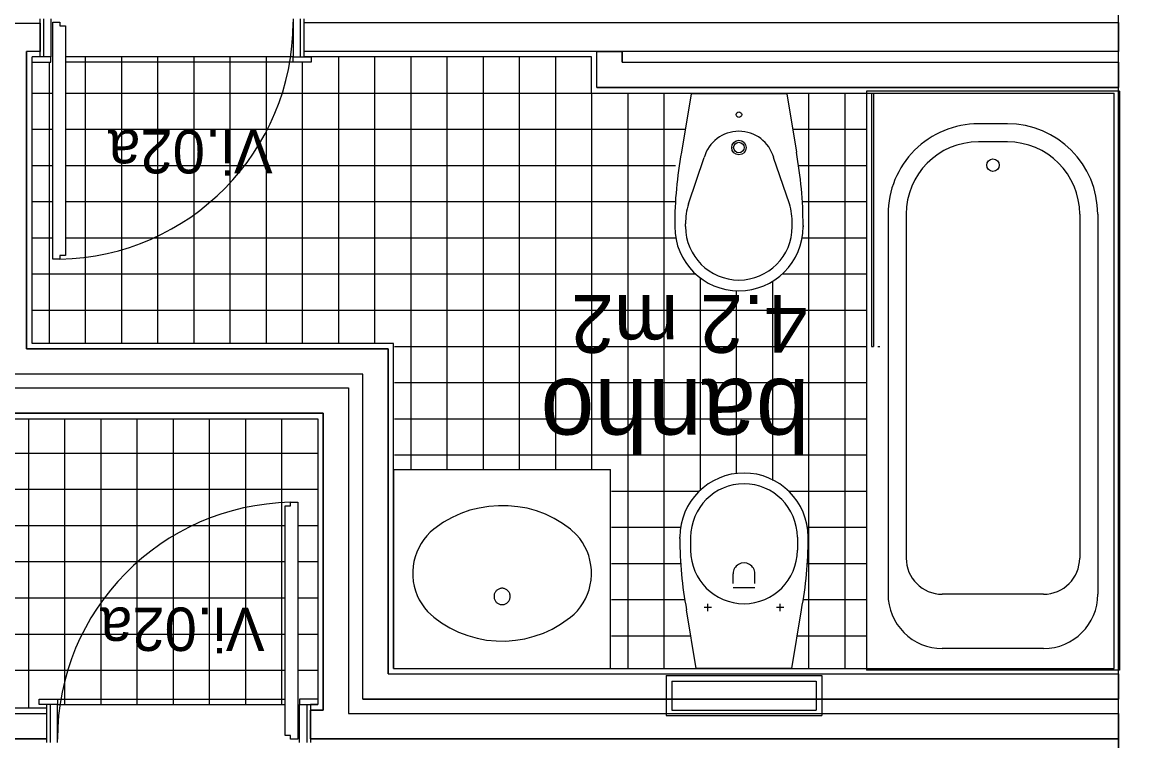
# Model space of a CAD drawing. Extents: x 1278 to 1356, y -253.7 to -224.
# Drawn here: x 1320.769 to 1323.824, y -240.419 to -238.433 of the extents above; entities that cross this region are included whole.
import ezdxf

# ---------------------------------------------------------------- set-up
doc = ezdxf.new("R2010")
doc.units = 0
for name, color, linetype in [('Level 1', 7, 'Continuous'), ('Level 10', 7, 'Continuous'), ('Level 11', 7, 'Continuous'), ('Level 13', 7, 'Continuous'), ('Level 2', 7, 'Continuous'), ('Level 36', 7, 'Continuous'), ('Level 4', 7, 'Continuous'), ('Level 40', 7, 'Continuous'), ('Level 60', 7, 'Continuous'), ('Level 65', 7, 'Continuous'), ('Level 66', 7, 'Continuous'), ('Level 67', 7, 'Continuous')]:
    doc.layers.add(name, color=color, linetype=linetype)

msp = doc.modelspace()

# ---------------------------------------------------------------- linework, layer by layer
at = {"layer": 'Level 1'}
for p, q in [((1320.8183, -238.529), (1320.8183, -238.424)), ((1321.5483, -238.529), (1321.5483, -238.424)), ((1320.7283, -238.4357), (1320.8183, -238.4357)), ((1321.5483, -238.434), (1323.801, -238.434)), ((1320.781, -239.3357), (1320.781, -238.514)), ((1322.3583, -238.514), (1321.5483, -238.514)), ((1323.801, -238.514), (1322.4283, -238.514)), ((1320.8183, -238.529), (1320.796, -238.529)), ((1321.781, -239.3357), (1320.781, -239.3357)), ((1321.781, -240.234), (1321.781, -239.3357)), ((1321.711, -239.4057), (1320.711, -239.4057)), ((1321.711, -240.304), (1321.711, -239.4057)), ((1320.671, -239.444), (1321.671, -239.444)), ((1321.671, -239.444), (1321.671, -240.344)), ((1320.601, -239.514), (1321.601, -239.514)), ((1321.601, -239.514), (1321.601, -240.334)), ((1321.7833, -240.234), (1323.801, -240.234)), ((1320.836, -240.319), (1320.836, -240.424)), ((1321.566, -240.319), (1321.566, -240.424)), ((1321.601, -240.334), (1321.566, -240.334)), ((1321.671, -240.344), (1323.801, -240.344)), ((1320.726, -240.414), (1320.836, -240.414)), ((1321.566, -240.414), (1323.801, -240.414)), ((1323.801, -240.414), (1323.801, -242.034))]:
    msp.add_line(p, q, dxfattribs=at)
at = {"layer": 'Level 10'}
for p, q in [((1320.8433, -238.544), (1320.8433, -239.319)), ((1321.5183, -238.529), (1320.8883, -238.529)), ((1320.9433, -238.529), (1320.9433, -239.319)), ((1321.0433, -238.529), (1321.0433, -239.319)), ((1321.1433, -238.529), (1321.1433, -239.319)), ((1321.2433, -238.529), (1321.2433, -239.319)), ((1321.3433, -238.529), (1321.3433, -239.319)), ((1321.4433, -238.529), (1321.4433, -239.319)), ((1321.5433, -238.544), (1321.5433, -239.319)), ((1321.6433, -238.529), (1321.6433, -239.319)), ((1321.7433, -238.529), (1321.7433, -239.319)), ((1321.8433, -238.529), (1321.8433, -239.669)), ((1321.9433, -238.529), (1321.9433, -239.669)), ((1322.0433, -238.529), (1322.0433, -239.669)), ((1322.1433, -238.529), (1322.1433, -239.669)), ((1322.2433, -238.529), (1322.2433, -239.669)), ((1320.7983, -238.629), (1320.8533, -238.629)), ((1320.8883, -238.629), (1322.602, -238.629)), ((1322.3433, -238.629), (1322.3433, -239.669)), ((1322.4433, -238.629), (1322.4433, -240.219)), ((1322.5433, -238.629), (1322.5433, -240.219)), ((1322.8995, -238.629), (1323.1033, -238.629)), ((1322.9433, -238.629), (1322.9433, -240.219)), ((1323.0433, -238.629), (1323.0433, -240.219)), ((1320.7983, -238.729), (1320.8533, -238.729)), ((1320.8883, -238.729), (1322.6023, -238.729)), ((1322.8992, -238.729), (1323.1033, -238.729)), ((1320.7983, -238.829), (1320.8533, -238.829)), ((1320.8883, -238.829), (1322.5751, -238.829)), ((1322.9158, -238.829), (1323.1033, -238.829)), ((1320.7983, -238.929), (1320.8533, -238.929)), ((1320.8883, -238.929), (1322.5763, -238.929)), ((1322.9253, -238.929), (1323.1033, -238.929)), ((1320.7983, -239.029), (1320.8533, -239.029)), ((1320.8883, -239.029), (1322.576, -239.029)), ((1322.9256, -239.029), (1323.1033, -239.029)), ((1320.7983, -239.129), (1322.6307, -239.129)), ((1322.8708, -239.129), (1323.1033, -239.129)), ((1322.6433, -239.1395), (1322.6433, -239.7272)), ((1322.8433, -239.1502), (1322.8433, -239.7)), ((1322.7433, -239.1756), (1322.7433, -239.6803)), ((1320.7983, -239.229), (1323.1033, -239.229)), ((1321.7983, -239.329), (1323.1033, -239.329)), ((1321.7983, -239.429), (1323.1033, -239.429)), ((1320.786, -239.529), (1320.786, -240.329)), ((1320.886, -239.529), (1320.886, -240.319)), ((1320.986, -239.529), (1320.986, -240.319)), ((1321.086, -239.529), (1321.086, -240.319)), ((1321.186, -239.529), (1321.186, -240.319)), ((1321.286, -239.529), (1321.286, -240.319)), ((1321.386, -239.529), (1321.386, -240.319)), ((1321.486, -239.529), (1321.486, -240.319)), ((1321.7983, -239.529), (1323.1033, -239.529)), ((1319.2103, -239.624), (1321.586, -239.624)), ((1321.7983, -239.629), (1323.1033, -239.629)), ((1319.8012, -239.724), (1321.586, -239.724)), ((1322.3981, -239.729), (1322.6414, -239.729)), ((1322.8884, -239.729), (1323.1033, -239.729)), ((1319.8548, -239.824), (1321.496, -239.824)), ((1321.531, -239.824), (1321.586, -239.824)), ((1322.3981, -239.829), (1322.5895, -239.829)), ((1322.9403, -239.829), (1323.1033, -239.829)), ((1319.853, -239.924), (1321.496, -239.924)), ((1321.531, -239.924), (1321.586, -239.924)), ((1322.3981, -239.929), (1322.5897, -239.929)), ((1322.9401, -239.929), (1323.1033, -239.929)), ((1319.8422, -240.024), (1321.496, -240.024)), ((1321.531, -240.024), (1321.586, -240.024)), ((1322.3981, -240.029), (1322.6014, -240.029)), ((1322.9285, -240.029), (1323.1033, -240.029)), ((1319.8256, -240.124), (1321.496, -240.124)), ((1321.531, -240.124), (1321.586, -240.124)), ((1322.3981, -240.129), (1322.6178, -240.129)), ((1322.912, -240.129), (1323.1033, -240.129)), ((1320.086, -240.224), (1321.496, -240.224)), ((1321.531, -240.224), (1321.586, -240.224)), ((1320.866, -240.319), (1321.496, -240.319))]:
    msp.add_line(p, q, dxfattribs=at)
at = {"layer": 'Level 11'}
for p, q in [((1322.6185, -238.6307), (1322.5918, -238.7928)), ((1322.8831, -238.6307), (1322.6185, -238.6307)), ((1322.8831, -238.6307), (1322.9097, -238.7928)), ((1323.8033, -238.624), (1323.1033, -238.624)), ((1323.1033, -238.624), (1323.1033, -240.224)), ((1323.8033, -238.624), (1323.8033, -240.224)), ((1323.4933, -238.714), (1323.4133, -238.714)), ((1323.4933, -238.764), (1323.4133, -238.764)), ((1322.611, -238.9352), (1322.6546, -238.8073)), ((1322.8906, -238.9352), (1322.8469, -238.8073)), ((1323.1633, -238.964), (1323.1633, -240.014)), ((1323.2133, -238.964), (1323.2133, -239.914)), ((1323.6933, -238.964), (1323.6933, -239.914)), ((1323.7433, -238.964), (1323.7433, -240.014)), ((1322.5733, -238.9949), (1322.5733, -238.9985)), ((1322.6033, -238.9982), (1322.6033, -238.9901)), ((1322.8983, -238.9982), (1322.8983, -238.9901)), ((1322.9283, -238.9949), (1322.9283, -238.9985)), ((1322.0329, -239.7759), (1322.0069, -239.7816)), ((1322.0592, -239.7715), (1322.0329, -239.7759)), ((1322.0858, -239.7694), (1322.0592, -239.7715)), ((1322.1125, -239.7697), (1322.0858, -239.7694)), ((1322.139, -239.7723), (1322.1125, -239.7697)), ((1322.1654, -239.7763), (1322.139, -239.7723)), ((1322.1911, -239.7835), (1322.1654, -239.7763)), ((1321.9574, -239.8017), (1321.9342, -239.8149)), ((1321.9817, -239.7905), (1321.9574, -239.8017)), ((1322.0069, -239.7816), (1321.9817, -239.7905)), ((1322.2161, -239.793), (1322.1911, -239.7835)), ((1322.2401, -239.8047), (1322.2161, -239.793)), ((1322.2631, -239.8184), (1322.2401, -239.8047)), ((1321.9071, -239.8341), (1321.8971, -239.8428)), ((1321.9342, -239.8149), (1321.9071, -239.8341)), ((1322.2848, -239.8341), (1322.2631, -239.8184)), ((1322.302, -239.85), (1322.2848, -239.8341)), ((1321.8794, -239.8628), (1321.8719, -239.8738)), ((1321.8878, -239.8524), (1321.8794, -239.8628)), ((1321.8971, -239.8428), (1321.8878, -239.8524)), ((1322.3106, -239.8602), (1322.302, -239.85)), ((1322.3183, -239.8711), (1322.3106, -239.8602)), ((1322.5874, -239.8598), (1322.5874, -239.8562)), ((1322.6174, -239.8565), (1322.6174, -239.8926)), ((1322.9124, -239.8565), (1322.9124, -239.8926)), ((1322.9424, -239.8598), (1322.9424, -239.8562)), ((1321.8599, -239.8977), (1321.8555, -239.9104)), ((1321.8654, -239.8855), (1321.8599, -239.8977)), ((1321.8719, -239.8738), (1321.8654, -239.8855)), ((1322.3251, -239.8827), (1322.3183, -239.8711)), ((1322.3308, -239.8948), (1322.3251, -239.8827)), ((1322.3355, -239.9073), (1322.3308, -239.8948)), ((1321.8522, -239.9234), (1321.85, -239.9366)), ((1321.8555, -239.9104), (1321.8522, -239.9234)), ((1322.339, -239.9202), (1322.3355, -239.9073)), ((1322.3415, -239.9334), (1322.339, -239.9202)), ((1321.85, -239.9366), (1321.849, -239.95)), ((1321.849, -239.95), (1321.8491, -239.9638)), ((1322.3428, -239.9468), (1322.3415, -239.9334)), ((1322.3419, -239.9753), (1322.3429, -239.9606)), ((1322.3429, -239.9606), (1322.3428, -239.9468)), ((1322.7349, -239.9845), (1322.7349, -239.9572)), ((1322.7949, -239.9845), (1322.7949, -239.9573)), ((1321.8491, -239.9638), (1321.8504, -239.9784)), ((1321.8504, -239.9784), (1321.8529, -239.9916)), ((1322.3364, -240.0015), (1322.3397, -239.9885)), ((1322.3397, -239.9885), (1322.3419, -239.9753)), ((1321.8529, -239.9916), (1321.8564, -240.0045)), ((1321.8564, -240.0045), (1321.8611, -240.0171)), ((1321.8611, -240.0171), (1321.8668, -240.0292)), ((1322.0737, -240.0182), (1322.0736, -240.0202)), ((1322.0736, -240.0202), (1322.0737, -240.0221)), ((1322.074, -240.0162), (1322.0737, -240.0182)), ((1322.0744, -240.0143), (1322.074, -240.0162)), ((1322.075, -240.0124), (1322.0744, -240.0143)), ((1322.0757, -240.0106), (1322.075, -240.0124)), ((1322.0766, -240.0089), (1322.0757, -240.0106)), ((1322.0777, -240.0072), (1322.0766, -240.0089)), ((1322.0789, -240.0057), (1322.0777, -240.0072)), ((1322.0802, -240.0042), (1322.0789, -240.0057)), ((1322.0816, -240.0029), (1322.0802, -240.0042)), ((1322.0832, -240.0017), (1322.0816, -240.0029)), ((1322.0848, -240.0006), (1322.0832, -240.0017)), ((1322.0865, -239.9997), (1322.0848, -240.0006)), ((1322.0883, -239.999), (1322.0865, -239.9997)), ((1322.0902, -239.9984), (1322.0883, -239.999)), ((1322.0921, -239.9979), (1322.0902, -239.9984)), ((1322.094, -239.9977), (1322.0921, -239.9979)), ((1322.096, -239.9976), (1322.094, -239.9977)), ((1322.0979, -239.9977), (1322.096, -239.9976)), ((1322.0998, -239.9979), (1322.0979, -239.9977)), ((1322.1017, -239.9984), (1322.0998, -239.9979)), ((1322.1036, -239.999), (1322.1017, -239.9984)), ((1322.1054, -239.9997), (1322.1036, -239.999)), ((1322.1071, -240.0006), (1322.1054, -239.9997)), ((1322.1087, -240.0017), (1322.1071, -240.0006)), ((1322.1103, -240.0029), (1322.1087, -240.0017)), ((1322.1117, -240.0042), (1322.1103, -240.0029)), ((1322.113, -240.0057), (1322.1117, -240.0042)), ((1322.1142, -240.0072), (1322.113, -240.0057)), ((1322.1153, -240.0089), (1322.1142, -240.0072)), ((1322.1162, -240.0106), (1322.1153, -240.0089)), ((1322.1169, -240.0124), (1322.1162, -240.0106)), ((1322.1175, -240.0143), (1322.1169, -240.0124)), ((1322.1179, -240.0162), (1322.1175, -240.0143)), ((1322.1182, -240.0182), (1322.1179, -240.0162)), ((1322.1183, -240.0202), (1322.1182, -240.0182)), ((1322.1182, -240.0221), (1322.1183, -240.0202)), ((1322.3265, -240.0263), (1322.332, -240.0141)), ((1322.332, -240.0141), (1322.3364, -240.0015)), ((1322.7949, -239.9968), (1322.7349, -239.9968)), ((1323.5933, -240.014), (1323.3133, -240.014)), ((1321.8668, -240.0292), (1321.8736, -240.0407)), ((1321.8736, -240.0407), (1321.8813, -240.0516)), ((1321.8813, -240.0516), (1321.8899, -240.0618)), ((1322.0737, -240.0221), (1322.074, -240.0241)), ((1322.074, -240.0241), (1322.0744, -240.026)), ((1322.0744, -240.026), (1322.075, -240.0279)), ((1322.075, -240.0279), (1322.0757, -240.0297)), ((1322.0757, -240.0297), (1322.0766, -240.0314)), ((1322.0766, -240.0314), (1322.0777, -240.0331)), ((1322.0777, -240.0331), (1322.0789, -240.0347)), ((1322.0789, -240.0347), (1322.0802, -240.0361)), ((1322.0802, -240.0361), (1322.0816, -240.0374)), ((1322.0816, -240.0374), (1322.0832, -240.0386)), ((1322.0832, -240.0386), (1322.0848, -240.0397)), ((1322.0848, -240.0397), (1322.0865, -240.0406)), ((1322.0865, -240.0406), (1322.0883, -240.0414)), ((1322.0883, -240.0414), (1322.0902, -240.042)), ((1322.0902, -240.042), (1322.0921, -240.0424)), ((1322.0921, -240.0424), (1322.094, -240.0426)), ((1322.094, -240.0426), (1322.096, -240.0427)), ((1322.096, -240.0427), (1322.0979, -240.0426)), ((1322.0979, -240.0426), (1322.0998, -240.0424)), ((1322.0998, -240.0424), (1322.1017, -240.042)), ((1322.1017, -240.042), (1322.1036, -240.0414)), ((1322.1036, -240.0414), (1322.1054, -240.0406)), ((1322.1054, -240.0406), (1322.1071, -240.0397)), ((1322.1071, -240.0397), (1322.1087, -240.0386)), ((1322.1087, -240.0386), (1322.1103, -240.0374)), ((1322.1103, -240.0374), (1322.1117, -240.0361)), ((1322.1117, -240.0361), (1322.113, -240.0347)), ((1322.113, -240.0347), (1322.1142, -240.0331)), ((1322.1142, -240.0331), (1322.1153, -240.0314)), ((1322.1153, -240.0314), (1322.1162, -240.0297)), ((1322.1162, -240.0297), (1322.1169, -240.0279)), ((1322.1169, -240.0279), (1322.1175, -240.026)), ((1322.1175, -240.026), (1322.1179, -240.0241)), ((1322.1179, -240.0241), (1322.1182, -240.0221)), ((1322.3041, -240.0595), (1322.3125, -240.0491)), ((1322.3125, -240.0491), (1322.32, -240.038)), ((1322.32, -240.038), (1322.3265, -240.0263)), ((1322.6749, -240.0508), (1322.6549, -240.0508)), ((1322.6649, -240.0608), (1322.6649, -240.0408)), ((1322.8749, -240.0508), (1322.8549, -240.0508)), ((1322.8649, -240.0608), (1322.8649, -240.0408)), ((1321.8899, -240.0618), (1321.9071, -240.0778)), ((1321.9071, -240.0778), (1321.9288, -240.0935)), ((1322.2577, -240.0969), (1322.2848, -240.0778)), ((1322.2848, -240.0778), (1322.2948, -240.069)), ((1322.2948, -240.069), (1322.3041, -240.0595)), ((1322.6326, -240.219), (1322.606, -240.0569)), ((1322.8972, -240.219), (1322.9239, -240.0569)), ((1321.9288, -240.0935), (1321.9518, -240.1072)), ((1321.9518, -240.1072), (1321.9758, -240.1189)), ((1322.2102, -240.1213), (1322.2345, -240.1102)), ((1322.2345, -240.1102), (1322.2577, -240.0969)), ((1321.9758, -240.1189), (1322.0008, -240.1284)), ((1322.0008, -240.1284), (1322.0267, -240.1356)), ((1322.0267, -240.1356), (1322.0529, -240.1406)), ((1322.0529, -240.1406), (1322.0794, -240.1432)), ((1322.0794, -240.1432), (1322.1061, -240.1435)), ((1322.1061, -240.1435), (1322.1327, -240.1414)), ((1322.1327, -240.1414), (1322.1592, -240.137)), ((1322.1592, -240.137), (1322.185, -240.1303)), ((1322.185, -240.1303), (1322.2102, -240.1213)), ((1323.5933, -240.164), (1323.3133, -240.164)), ((1322.8972, -240.219), (1322.6326, -240.219)), ((1323.8033, -240.224), (1323.1033, -240.224)), ((1322.5499, -240.239), (1322.5499, -240.349)), ((1322.5499, -240.239), (1322.9799, -240.239)), ((1322.5649, -240.254), (1322.9649, -240.254)), ((1322.5649, -240.254), (1322.5649, -240.334)), ((1322.9649, -240.254), (1322.9649, -240.334)), ((1322.9799, -240.239), (1322.9799, -240.349)), ((1322.5499, -240.349), (1322.9799, -240.349)), ((1322.5649, -240.334), (1322.9649, -240.334))]:
    msp.add_line(p, q, dxfattribs=at)
for centre, radius in [((1322.7508, -238.6887), 0.00766), ((1322.7508, -238.7796), 0.02), ((1322.7508, -238.7796), 0.0146), ((1323.4533, -238.8284), 0.0173)]:
    msp.add_circle(centre, radius, dxfattribs=at)
for centre, radius, start, end in [((1322.7508, -238.8347), 0.1, 15.8047, 164.0683), ((1323.4133, -238.964), 0.25, 89.9999, 180), ((1323.4933, -238.964), 0.25, 0.0001, 90.0001), ((1323.4133, -238.964), 0.2, 90, 180), ((1323.4933, -238.964), 0.2, 360, 90), ((1322.8033, -238.9901), 0.2, 164.0681, 179.9983), ((1322.6983, -238.9901), 0.2, 359.9994, 15.9307), ((1322.7508, -238.9982), 0.1775, 180.0001, 359.9998), ((1322.7508, -238.9982), 0.1475, 180.0001, 359.9998), ((1322.7649, -239.8565), 0.1775, 0.0002, 179.9999), ((1322.7649, -239.8565), 0.1475, 0.0002, 179.9999), ((1322.7649, -239.8926), 0.1475, 180.0002, 359.9999), ((1322.7649, -239.9574), 0.03, 359.9995, 180.0013), ((1323.3133, -239.914), 0.1, 180.0001, 269.9999), ((1323.5933, -239.914), 0.1, 270, 0), ((1323.3133, -240.014), 0.15, 179.9998, 270.0001), ((1323.5933, -240.014), 0.15, 270, 0)]:
    msp.add_arc(centre, radius, start, end, dxfattribs=at)
for centre, major_axis, ratio, start_param, end_param in [((1323.9733, -238.9948), (-1.4, 0), 0.88995, 6.120269, 6.283187), ((1321.5283, -238.9948), (1.4, 0), 0.88995, 6.283183, 6.446102), ((1323.9874, -239.8598), (-1.4, 0), 0.867931, 6.283184, 6.446103), ((1321.5424, -239.8598), (1.4, 0), 0.867931, 6.120269, 6.283188)]:
    msp.add_ellipse(centre, major_axis=major_axis, ratio=ratio, start_param=start_param, end_param=end_param, dxfattribs=at)
at = {"layer": 'Level 13'}
for p, q in [((1320.8283, -238.529), (1320.8283, -238.424)), ((1320.8483, -238.424), (1320.8483, -238.529)), ((1321.5183, -238.424), (1321.5183, -238.529)), ((1321.5383, -238.529), (1321.5383, -238.424)), ((1320.8533, -239.0883), (1320.8533, -238.4333)), ((1320.8533, -238.4333), (1320.8733, -238.4333)), ((1320.8733, -238.4333), (1320.8733, -238.4433)), ((1320.8733, -238.4433), (1320.8883, -238.4433)), ((1320.8883, -238.4433), (1320.8883, -239.0783)), ((1320.8483, -238.529), (1320.7983, -238.529)), ((1320.7983, -238.544), (1320.8483, -238.544)), ((1320.8483, -238.529), (1320.8283, -238.529)), ((1320.8483, -238.544), (1320.8483, -238.529)), ((1321.5183, -238.544), (1321.5183, -238.529)), ((1321.5183, -238.529), (1321.5383, -238.529)), ((1321.5183, -238.529), (1321.5683, -238.529)), ((1321.5683, -238.544), (1321.5183, -238.544)), ((1321.5683, -238.529), (1321.5683, -238.544)), ((1320.8733, -239.0883), (1320.8533, -239.0883)), ((1320.8733, -239.0783), (1320.8733, -239.088)), ((1320.8883, -239.0783), (1320.8733, -239.0783)), ((1321.496, -240.4047), (1321.496, -239.7697)), ((1321.496, -239.7697), (1321.511, -239.7697)), ((1321.511, -239.7597), (1321.531, -239.7597)), ((1321.511, -239.7697), (1321.511, -239.76)), ((1321.531, -239.7597), (1321.531, -240.4147)), ((1320.816, -240.304), (1320.866, -240.304)), ((1320.816, -240.319), (1320.816, -240.304)), ((1320.866, -240.319), (1320.816, -240.319)), ((1320.846, -240.319), (1320.846, -240.424)), ((1320.866, -240.319), (1320.846, -240.319)), ((1320.866, -240.304), (1320.866, -240.319)), ((1320.866, -240.424), (1320.866, -240.319)), ((1321.586, -240.304), (1321.536, -240.304)), ((1321.536, -240.304), (1321.536, -240.319)), ((1321.536, -240.424), (1321.536, -240.319)), ((1321.536, -240.319), (1321.556, -240.319)), ((1321.536, -240.319), (1321.586, -240.319)), ((1321.556, -240.319), (1321.556, -240.424)), ((1321.511, -240.4047), (1321.496, -240.4047)), ((1321.511, -240.4147), (1321.511, -240.4047)), ((1321.531, -240.4147), (1321.511, -240.4147))]:
    msp.add_line(p, q, dxfattribs=at)
at = {"layer": 'Level 2'}
for p, q in [((1321.796, -239.669), (1322.3958, -239.669)), ((1321.796, -239.669), (1321.796, -240.219)), ((1322.3958, -240.219), (1322.3958, -239.669))]:
    msp.add_line(p, q, dxfattribs=at)
at = {"layer": 'Level 36'}
for p, q in [((1323.1177, -238.629), (1323.1177, -239.329)), ((1323.1227, -238.629), (1323.1227, -239.329)), ((1323.1177, -239.329), (1323.1227, -239.329)), ((1323.1354, -239.329), (1323.1404, -239.329))]:
    msp.add_line(p, q, dxfattribs=at)
at = {"layer": 'Level 4'}
for p, q in [((1321.5183, -238.544), (1320.8883, -238.544)), ((1320.866, -240.304), (1321.496, -240.304))]:
    msp.add_line(p, q, dxfattribs=at)
for centre, major_axis in [((1320.8596, -238.4333), (-0.6586, 0)), ((1321.5247, -240.4147), (0.6586, 0))]:
    msp.add_ellipse(centre, major_axis=major_axis, ratio=0.994279, start_param=1.591512, end_param=3.141593, dxfattribs=at)
at = {"layer": 'Level 65'}
for p, q in [((1320.796, -239.3207), (1320.796, -238.529)), ((1322.3433, -238.529), (1321.5483, -238.529)), ((1322.3433, -238.629), (1322.3433, -238.529)), ((1322.3433, -238.629), (1323.7883, -238.629)), ((1323.7883, -240.219), (1323.7883, -238.629)), ((1321.796, -239.3207), (1320.796, -239.3207)), ((1321.796, -240.219), (1321.796, -239.3207)), ((1320.586, -239.529), (1321.586, -239.529)), ((1321.586, -239.529), (1321.586, -240.319)), ((1321.796, -240.219), (1323.7883, -240.219)), ((1321.586, -240.319), (1321.566, -240.319)), ((1320.836, -240.329), (1320.086, -240.329))]:
    msp.add_line(p, q, dxfattribs=at)
at = {"layer": 'Level 66'}
for p, q in [((1323.801, -238.434), (1323.801, -236.814)), ((1320.8183, -238.514), (1320.781, -238.514)), ((1322.3583, -238.614), (1322.3583, -238.514)), ((1322.4283, -238.544), (1322.4283, -238.514)), ((1323.801, -238.544), (1323.801, -238.514)), ((1322.4283, -238.544), (1323.801, -238.544)), ((1322.3583, -238.614), (1323.801, -238.614)), ((1323.801, -240.234), (1323.801, -238.614)), ((1321.781, -240.234), (1323.801, -240.234)), ((1321.711, -240.304), (1323.801, -240.304)), ((1323.801, -240.344), (1323.801, -240.304)), ((1320.071, -240.344), (1320.836, -240.344))]:
    msp.add_line(p, q, dxfattribs=at)
at = {"layer": 'Level 67'}
for points in [[(1323.871, -242.1713), (1323.801, -242.1713), (1323.801, -236.7713), (1323.871, -236.7713), (1323.871, -242.1713)], [(1323.801, -238.434), (1323.801, -238.514), (1321.5483, -238.514), (1321.5483, -238.434)], [(1323.801, -238.544), (1323.801, -238.614), (1322.3583, -238.614), (1322.3583, -238.514), (1322.4283, -238.514), (1322.4283, -238.544)], [(1323.801, -240.414), (1321.566, -240.414), (1321.566, -240.334), (1321.601, -240.334), (1321.601, -239.514), (1320.601, -239.514), (1320.601, -238.614), (1318.5133, -238.614), (1318.5133, -238.544), (1320.671, -238.544), (1320.671, -239.444), (1321.671, -239.444), (1321.671, -240.344), (1323.801, -240.344)], [(1320.836, -240.414), (1319.621, -240.414), (1319.621, -240.344), (1320.836, -240.344)]]:
    msp.add_lwpolyline(points, close=True, dxfattribs=at)
msp.add_lwpolyline([(1320.7283, -237.724), (1320.7283, -238.4357), (1320.8183, -238.4357), (1320.8183, -238.514), (1320.781, -238.514), (1320.781, -239.3357), (1321.781, -239.3357), (1321.781, -240.234), (1323.801, -240.234), (1323.801, -240.304), (1321.711, -240.304), (1321.711, -239.4057), (1320.711, -239.4057), (1320.711, -238.5057), (1319.551, -238.5057), (1319.551, -238.244)], dxfattribs=at)

# ---------------------------------------------------------------- texts
at = {"layer": 'Level 40'}
for p in [(1321.4614, -238.731), (1321.439, -240.0507)]:
    msp.add_text('Vi.02a', height=0.12, rotation=180, dxfattribs=at).set_placement(p)
at = {"layer": 'Level 60'}
for s, height, p in [('4.2 m2', 0.16, (1322.9406, -239.1869)), ('banho', 0.2, (1322.9462, -239.4192))]:
    msp.add_text(s, height=height, rotation=180, dxfattribs=at).set_placement(p)

doc.saveas('drawing.dxf')
